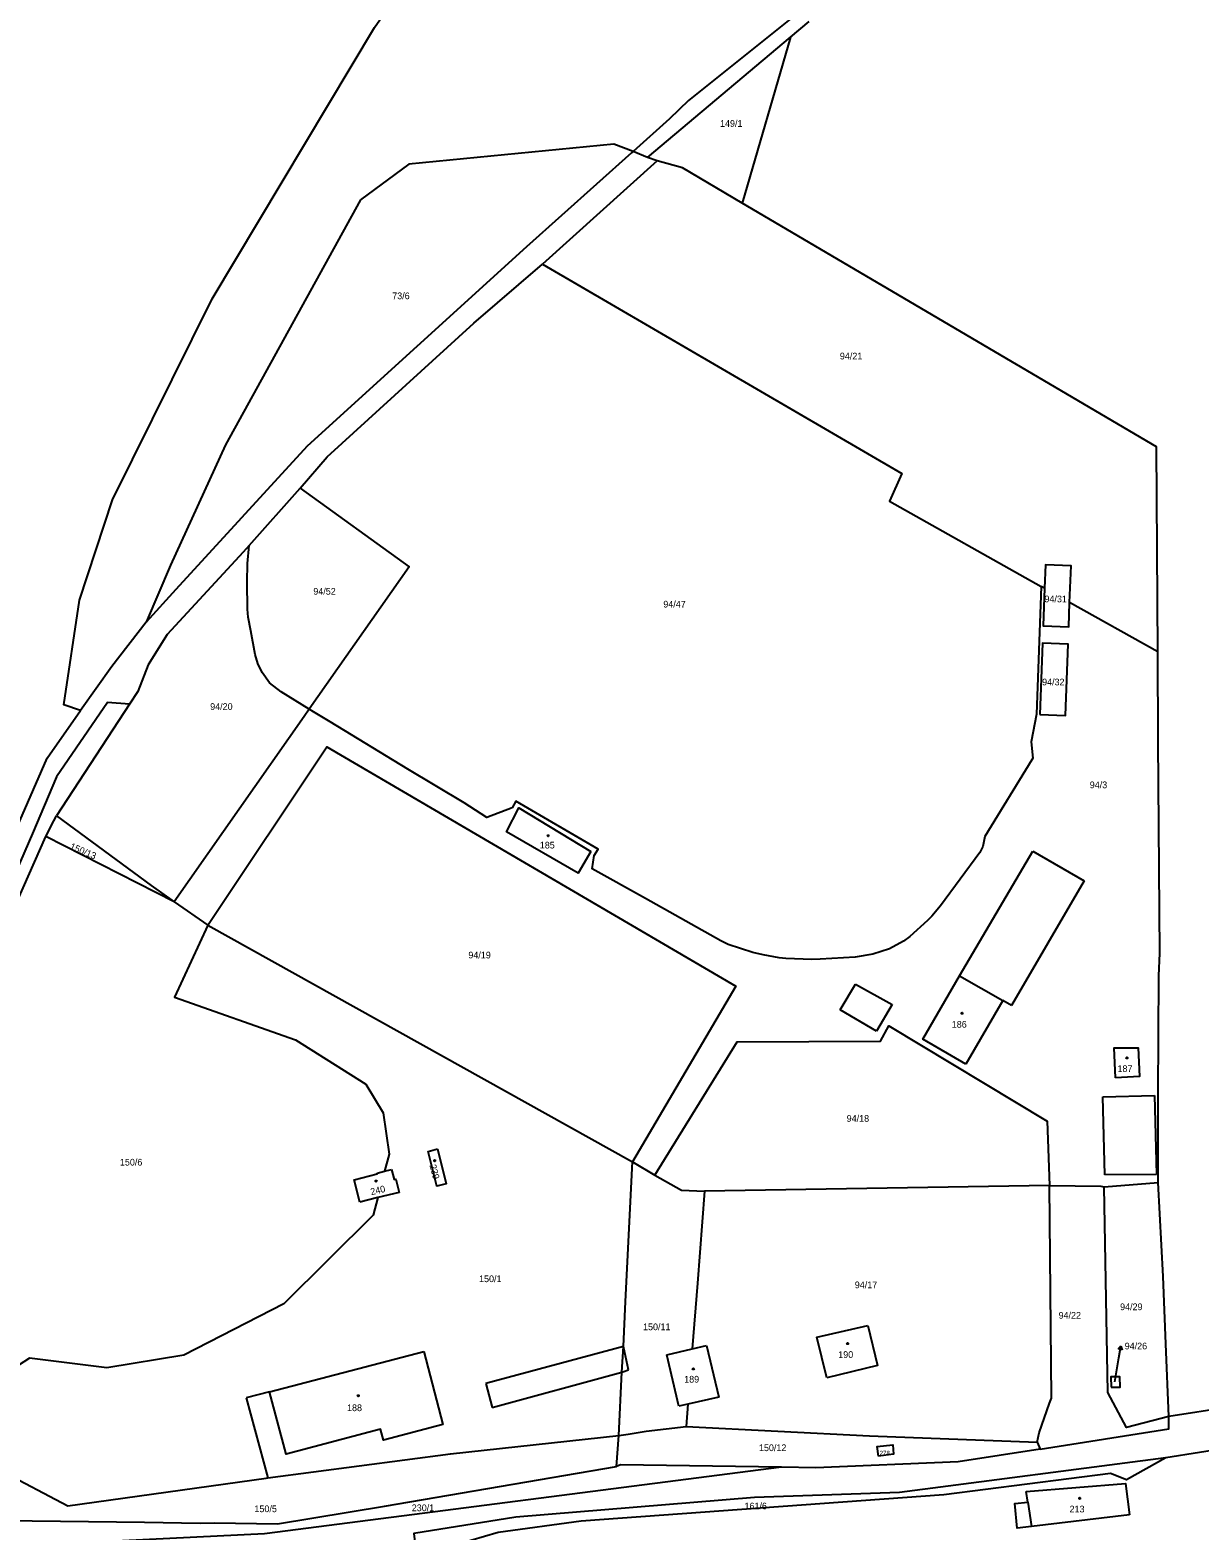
# Model space of a CAD drawing. Extents: x -670359 to -660124, y -978807 to -970072.
# Drawn here: x -662233.7 to -661937, y -971196.2 to -970815.7 of the extents above; entities that cross this region are included whole.
import ezdxf

# ---------------------------------------------------------------- set-up
doc = ezdxf.new("R2010")
doc.units = 0
for name, color, linetype in [('Hranice parcel', 7, 'Continuous'), ('Parcelní čísla', 7, 'Continuous'), ('Pop  PČ popisy', 7, 'Continuous'), ('Vnitřní kresba', 7, 'Continuous'), ('Značky budov', 7, 'Continuous')]:
    doc.layers.add(name, color=color, linetype=linetype)

# ---------------------------------------------------------------- blocks, each defined once
blk = doc.blocks.new('4.02')
at = {"layer": 'Značky budov'}
blk.add_circle((-0.01, 0), 0.175, dxfattribs=at)
blk = doc.blocks.new('1029_271')
at = {"layer": 'Pop  PČ popisy'}
for p, q in [((0.47, 2.96), (-0.18, 2.05)), ((0, 0), (0.47, 2.96)), ((0.47, 2.96), (0.81, 1.9))]:
    blk.add_line(p, q, dxfattribs=at)

msp = doc.modelspace()

# ---------------------------------------------------------------- linework, layer by layer
at = {"layer": 'Hranice parcel'}
for p, q in [((-662040.66, -970817.51), (-662035.98, -970813.57)), ((-662077.02, -970848.08), (-662040.66, -970817.51)), ((-662040.66, -970817.51), (-662052.92, -970859.68)), ((-662080.63, -970846.53), (-662085.51, -970844.66)), ((-662080.63, -970846.53), (-662081.02, -970846.88)), ((-662074.52, -970848.88), (-662077.02, -970848.08)), ((-662074.52, -970848.88), (-662103.6, -970875.13)), ((-662178.05, -970946.47), (-662165.16, -970931.98)), ((-662178.5, -970951.05), (-662178.05, -970946.47)), ((-661977.06, -970956.88), (-661978.31, -970989.27)), ((-661976.24, -970957.34), (-661977.06, -970956.88)), ((-661947.51, -970973.47), (-661969.86, -970960.92)), ((-662204.2, -970965.92), (-662212.94, -970977.16)), ((-662212.94, -970977.16), (-662220.82, -970988.37)), ((-662162.81, -970987.99), (-662169.91, -970983.64)), ((-662229.31, -971000.46), (-662220.82, -970988.37)), ((-662208.42, -970986.78), (-662226.92, -971015.08)), ((-662161.7, -970988.67), (-662162.81, -970987.99)), ((-662237.66, -971019.61), (-662229.31, -971000.46)), ((-662197.1, -971036.93), (-662229.69, -971020.32)), ((-662197.1, -971036.93), (-662188.51, -971042.8)), ((-662188.51, -971042.8), (-662080.79, -971102.88)), ((-662082.53, -971138.27), (-662080.79, -971102.88)), ((-662080.79, -971102.88), (-662075.13, -971106.24)), ((-662145.62, -971105.72), (-662143.68, -971105.22)), ((-662143.68, -971105.22), (-662141.94, -971104.78)), ((-662140.02, -971110.61), (-662145.44, -971111.93)), ((-661974.97, -971108.85), (-662062.56, -971110.25)), ((-661974.97, -971108.85), (-661961.95, -971109.02)), ((-661961.95, -971109.02), (-661961.11, -971109.22)), ((-661961.11, -971109.22), (-661947.39, -971108.1)), ((-662145.44, -971111.93), (-662150.01, -971113.05)), ((-662072.06, -971151.82), (-662065.62, -971150.28)), ((-662069.02, -971164.86), (-662072.06, -971151.82)), ((-662065.62, -971150.28), (-662062.05, -971149.43)), ((-662062.05, -971149.43), (-662058.92, -971162.51)), ((-662058.92, -971162.51), (-662066.72, -971164.32)), ((-662066.72, -971164.32), (-662069.02, -971164.86)), ((-662066.72, -971164.32), (-662067.16, -971170.03)), ((-661929.34, -971165.12), (-661944.72, -971167.49)), ((-662077.3, -971171.14), (-662067.16, -971170.03)), ((-661889.77, -971169.15), (-661945.43, -971177.96)), ((-662084.85, -971180.15), (-662084.27, -971172.29)), ((-661978.12, -971173.96), (-661977.35, -971175.75)), ((-662083.8, -971179.74), (-662084.85, -971180.15)), ((-662042.95, -971180.34), (-662083.8, -971179.74))]:
    msp.add_line(p, q, dxfattribs=at)
for points in [[(-662220.82, -970988.37), (-662225.09, -970986.95), (-662221.1, -970960.34), (-662212.74, -970934.93), (-662187.44, -970883.96), (-662146.29, -970815.07), (-662108.24, -970760.52), (-662102.78, -970751.11)], [(-662027.19, -970789.97), (-662039.11, -970811.64), (-662066.54, -970833.6)], [(-662066.54, -970833.6), (-662071.39, -970838.28), (-662080.63, -970846.53)], [(-662081.02, -970846.88), (-662107.67, -970870.7), (-662163.37, -970921.3), (-662196.65, -970957.65), (-662204.2, -970965.92)], [(-662085.51, -970844.66), (-662137.58, -970849.78), (-662149.77, -970858.8)], [(-662052.92, -970859.68), (-662068.09, -970850.66), (-662074.52, -970848.88)], [(-662149.77, -970858.8), (-662184.08, -970920.98), (-662198.05, -970951.45), (-662204.2, -970965.92)], [(-661947.51, -970973.47), (-661947.82, -970921.49), (-662052.92, -970859.68)], [(-662165.16, -970931.98), (-662158.29, -970924.03), (-662121.07, -970890.12), (-662103.6, -970875.13)], [(-662103.6, -970875.13), (-662012.45, -970928.27), (-662015.57, -970935.24), (-661977.06, -970956.88)], [(-662165.16, -970931.98), (-662137.48, -970951.91), (-662162.81, -970987.99)], [(-662178.05, -970946.47), (-662179.6, -970948.21), (-662198.91, -970969.09), (-662203.7, -970976.74), (-662206.3, -970983.5), (-662208.42, -970986.78)], [(-662169.91, -970983.64), (-662172.86, -970981.34), (-662174.8, -970978.74), (-662175.86, -970976.46), (-662176.5, -970974.13), (-662177.66, -970968.16), (-662178.32, -970964.66), (-662178.52, -970962.66), (-662178.6, -970955.8), (-662178.5, -970951.05)], [(-661969.86, -970960.92), (-661969.51, -970951.66), (-661976.02, -970951.44), (-661976.24, -970957.34)], [(-661976.24, -970957.34), (-661976.59, -970966.91), (-661970.09, -970967.15), (-661969.86, -970960.92)], [(-661977.41, -970989.38), (-661970.93, -970989.66), (-661970.23, -970971.56), (-661976.73, -970971.3), (-661977.41, -970989.38)], [(-661947.39, -971108.1), (-661947.36, -971085.74), (-661947.26, -971055.69), (-661946.98, -971049.92), (-661947.43, -970996.26), (-661947.51, -970973.47)], [(-662208.42, -970986.78), (-662214.05, -970986.34), (-662226.94, -971005.17), (-662233.05, -971019.55), (-662250.19, -971058.98), (-662255.61, -971071.61), (-662259.92, -971132.48), (-662264.42, -971161.48), (-662272.61, -971183.68), (-662270.55, -971189.92)], [(-662162.81, -970987.99), (-662164.12, -970989.86), (-662197.1, -971036.93)], [(-661978.31, -970989.27), (-661979.62, -970996.29), (-661979.18, -971000.49), (-661979.43, -971000.9), (-661991.37, -971020.36), (-661991.93, -971022.86), (-661992.64, -971024.4), (-662002.59, -971037.88), (-662004.84, -971040.55), (-662005.89, -971041.65), (-662010.38, -971045.67), (-662011.99, -971046.87), (-662015.55, -971048.78), (-662019.8, -971050.17), (-662024.25, -971050.94), (-662033.18, -971051.48), (-662035.24, -971051.5), (-662041.89, -971051.31), (-662043.53, -971051.13), (-662047.66, -971050.36), (-662050.29, -971049.76), (-662056.55, -971047.72), (-662058.4, -971046.8), (-662077.52, -971036.02), (-662091.01, -971028.51), (-662090.52, -971025.13), (-662089.47, -971023.53), (-662110.41, -971011.38), (-662111.36, -971013.01), (-662117.75, -971015.46), (-662123.5, -971011.75), (-662137.84, -971003.23), (-662157.49, -970991.27), (-662161.7, -970988.67)], [(-662188.51, -971042.8), (-662158.32, -970997.57), (-662054.56, -971058.25), (-662080.79, -971102.88)], [(-662229.69, -971020.32), (-662227.59, -971016.37), (-662226.92, -971015.08)], [(-662226.92, -971015.08), (-662202.89, -971032.78), (-662197.1, -971036.93)], [(-662091.36, -971024.15), (-662094.58, -971029.63), (-662112.79, -971019.17), (-662109.66, -971013.09), (-662091.36, -971024.15)], [(-662256.01, -971129.85), (-662255.58, -971115.76), (-662253.45, -971073.88), (-662245.39, -971055.79), (-662229.69, -971020.32)], [(-662188.51, -971042.8), (-662196.99, -971061.08), (-662166.33, -971071.91), (-662148.47, -971083.18), (-662144.06, -971090.41), (-662142.56, -971100.94), (-662143.68, -971105.22)], [(-661996.17, -971078.08), (-662007.11, -971071.7), (-661997.78, -971055.64), (-661986.81, -971061.95), (-661996.17, -971078.08)], [(-662075.13, -971106.24), (-662054.27, -971072.39), (-662017.87, -971072.27), (-662015.74, -971068.36), (-661975.57, -971092.5), (-661974.97, -971108.85)], [(-661958.23, -971081.51), (-661958.55, -971073.96), (-661952.49, -971073.9), (-661952.13, -971081.2), (-661958.23, -971081.51)], [(-662130.3, -971099.59), (-662128.05, -971108.4), (-662130.41, -971109.02), (-662132.68, -971100.22), (-662130.3, -971099.59)], [(-662150.01, -971113.05), (-662151.43, -971107.38), (-662145.58, -971105.89), (-662145.62, -971105.72)], [(-662141.94, -971104.78), (-662141.29, -971107.36), (-662140.87, -971107.25), (-662140.02, -971110.61)], [(-662075.13, -971106.24), (-662068.35, -971110.05), (-662062.56, -971110.25)], [(-662062.56, -971110.25), (-662064.33, -971133.67), (-662065.62, -971150.28)], [(-661978.12, -971173.96), (-661977.58, -971171.56), (-661974.96, -971164.04), (-661974.5, -971162.79), (-661974.97, -971108.85)], [(-661944.72, -971167.49), (-661955.45, -971170.24), (-661960.18, -971161.33), (-661961.11, -971109.22)], [(-661944.72, -971167.49), (-661945.43, -971149.05), (-661946.11, -971131.95), (-661947.39, -971108.1)], [(-662145.44, -971111.93), (-662146.6, -971116.37), (-662169.28, -971138.89), (-662194.66, -971151.86), (-662214.19, -971155.08), (-662233.8, -971152.68), (-662239.8, -971156.58), (-662257.8, -971155.77)], [(-662084.27, -971172.29), (-662083.48, -971156.21), (-662083.04, -971149.69), (-662082.53, -971138.27)], [(-662031.49, -971157.62), (-662033.98, -971147.36), (-662021.03, -971144.36)], [(-662021.03, -971144.36), (-662018.59, -971154.51), (-662031.49, -971157.62)], [(-662133.76, -971150.94), (-662128.9, -971169.51), (-662143.98, -971173.47), (-662144.71, -971170.7), (-662168.64, -971177.03), (-662172.89, -971161.18), (-662133.76, -971150.94)], [(-662257.8, -971155.77), (-662258.14, -971172.15), (-662224.09, -971190.09), (-662173.76, -971183.1), (-662173.36, -971183.05), (-662126.97, -971176.96), (-662084.27, -971172.29)], [(-661959.35, -971160.03), (-661957.08, -971160.01), (-661957.13, -971157.36), (-661959.41, -971157.43), (-661959.35, -971160.03)], [(-661977.35, -971175.75), (-661944.72, -971170.62), (-661944.72, -971167.49)], [(-662084.27, -971172.29), (-662081.93, -971171.97), (-662077.3, -971171.14)], [(-662067.16, -971170.03), (-662020.61, -971172.38), (-661978.12, -971173.96)], [(-662018.37, -971177.51), (-662018.67, -971175.05), (-662014.76, -971174.61), (-662014.52, -971177.05), (-662018.37, -971177.51)], [(-661945.43, -971177.96), (-662013.02, -971186.75), (-662049.86, -971188.01), (-662110.43, -971193.02), (-662136.25, -971197.11), (-662135.8, -971201.42)], [(-661945.43, -971177.96), (-661955.43, -971183.54), (-661959.52, -971181.95), (-662001.82, -971187.34), (-662093.79, -971193.98), (-662114.84, -971196.86), (-662125.31, -971199.94)], [(-661977.35, -971175.75), (-661998.12, -971178.97), (-662034.27, -971180.47), (-662042.95, -971180.34)], [(-662260.29, -971192.33), (-662254.56, -971193.7), (-662204.59, -971194.23), (-662190.49, -971194.53), (-662186.84, -971194.43), (-662170.91, -971194.68), (-662143.69, -971190.23), (-662084.85, -971180.15)], [(-662042.95, -971180.34), (-662174.13, -971197.23), (-662246.36, -971200.75), (-662254.62, -971201.15), (-662259.2, -971201.37)], [(-661954.71, -971192.41), (-661979.54, -971195.32), (-661983.14, -971195.74), (-661983.75, -971189.51), (-661980.45, -971189.19), (-661980.86, -971186.44)], [(-661980.86, -971186.44), (-661955.67, -971184.42), (-661954.71, -971192.41)]]:
    msp.add_lwpolyline(points, dxfattribs=at)
at = {"layer": 'Pop  PČ popisy'}
msp.add_line((-661958.39, -971158.7), (-661957.38, -971152.54), dxfattribs=at)
at = {"layer": 'Vnitřní kresba'}
for p, q in [((-662077.02, -970848.08), (-662080.63, -970846.53)), ((-661997.78, -971055.64), (-661979.24, -971024.08)), ((-661979.24, -971024.08), (-661966.2, -971031.58)), ((-661966.2, -971031.58), (-661984.59, -971063.18)), ((-662028.07, -971064.31), (-662024.16, -971057.81)), ((-662024.16, -971057.81), (-662014.91, -971062.98)), ((-662018.88, -971069.72), (-662028.07, -971064.31)), ((-662014.91, -971062.98), (-662018.88, -971069.72)), ((-661984.59, -971063.18), (-661986.81, -971061.95)), ((-661961.48, -971086.39), (-661948.31, -971086.04)), ((-661960.96, -971106.16), (-661961.48, -971086.39)), ((-661948.31, -971086.04), (-661947.78, -971106.09)), ((-661947.78, -971106.09), (-661960.96, -971106.16)), ((-662083.04, -971149.69), (-662117.98, -971159.08)), ((-662081.8, -971155.62), (-662083.04, -971149.69)), ((-662116.38, -971165.18), (-662083.48, -971156.21)), ((-662083.48, -971156.21), (-662083.26, -971156.13)), ((-662083.26, -971156.13), (-662081.8, -971155.62)), ((-662117.98, -971159.08), (-662116.38, -971165.18)), ((-662172.89, -971161.18), (-662178.86, -971162.7)), ((-662178.86, -971162.7), (-662173.36, -971183.05)), ((-661980.45, -971189.19), (-661979.54, -971195.32))]:
    msp.add_line(p, q, dxfattribs=at)

# ---------------------------------------------------------------- block references
at = {"layer": 'Pop  PČ popisy'}
msp.add_blockref('1029_271', (-661957.38, -971152.54), dxfattribs=at)
at = {"layer": 'Značky budov'}
for p in [(-662102.18, -971020.12), (-661997.16, -971065.16), (-661955.31, -971076.5), (-662130.97, -971102.56), (-662145.83, -971107.74), (-662026.21, -971148.94), (-662065.34, -971155.39), (-662150.38, -971162.2), (-661967.29, -971188.21)]:
    msp.add_blockref('4.02', p, dxfattribs=at)

# ---------------------------------------------------------------- texts
at = {"layer": 'Parcelní čísla'}
for s, height, p in [('149/1', 1.7, (-662058.58, -970840.3)), ('73/6', 1.7, (-662141.76, -970884.02)), ('94/21', 1.7, (-662028.17, -970899.3)), ('94/52', 1.7, (-662161.78, -970958.98)), ('94/47', 1.7, (-662072.97, -970962.24)), ('94/31', 1.7, (-661976.25, -970960.91)), ('94/32', 1.7, (-661976.85, -970981.98)), ('94/20', 1.7, (-662187.95, -970988.21)), ('94/3', 1.7, (-661964.76, -971008.07)), ('185', 1.7, (-662104.31, -971023.36)), ('94/19', 1.7, (-662122.44, -971051.25)), ('186', 1.7, (-661999.77, -971068.83)), ('187', 1.7, (-661957.72, -971080.07)), ('94/18', 1.7, (-662026.44, -971092.7)), ('150/6', 1.7, (-662210.86, -971103.79)), ('150/1', 1.7, (-662119.72, -971133.37)), ('94/17', 1.7, (-662024.38, -971134.91)), ('94/22', 1.7, (-661972.67, -971142.63)), ('94/29', 1.7, (-661957.06, -971140.48)), ('150/11', 1.7, (-662078.11, -971145.56)), ('94/26', 1.7, (-661955.89, -971150.43)), ('190', 1.7, (-662028.58, -971152.59)), ('189', 1.7, (-662067.67, -971158.85)), ('188', 1.7, (-662153.22, -971166.09)), ('150/12', 1.7, (-662048.7, -971176.23)), ('278', 1.14, (-662018.1, -971177.3)), ('150/5', 1.7, (-662176.72, -971191.72)), ('230/1', 1.7, (-662136.8, -971191.47)), ('161/6', 1.7, (-662052.36, -971191.02)), ('213', 1.7, (-661969.88, -971191.78))]:
    msp.add_text(s, height=height, dxfattribs=at).set_placement(p)
for s, rotation, p in [('150/13', 337, (-662223.72, -971023.45)), ('239', 285, (-662132.32, -971103.75)), ('240', 13, (-662147.08, -971111.32))]:
    msp.add_text(s, height=1.7, rotation=rotation, dxfattribs=at).set_placement(p)

doc.saveas('drawing.dxf')
